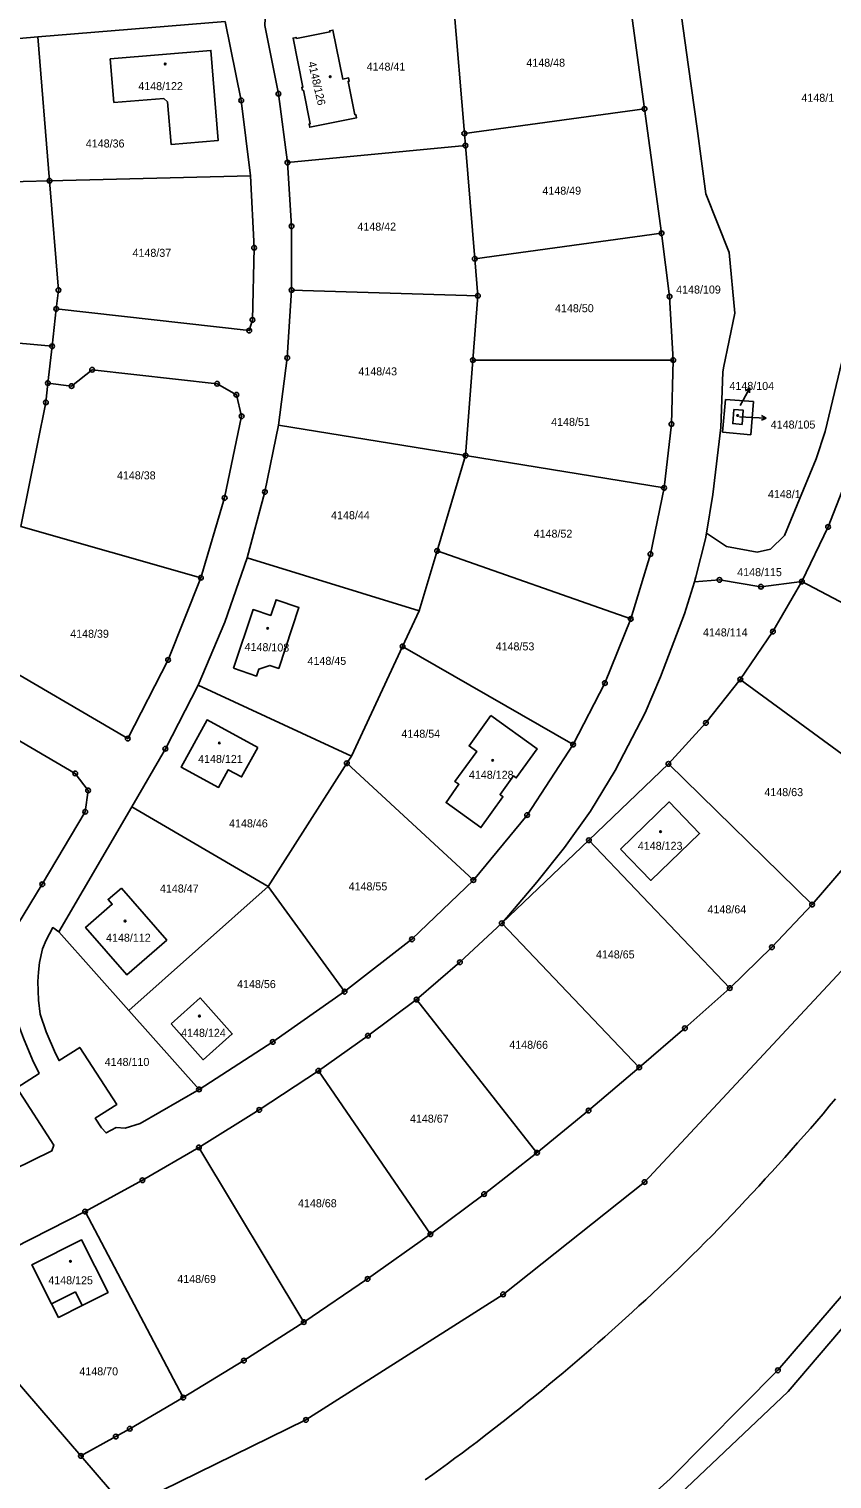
# Model space of a CAD drawing. Extents: x -733394 to -722299, y -1082822 to -1075049.
# Drawn here: x -728749.3 to -728578.8, y -1081434.3 to -1081126.2 of the extents above; entities that cross this region are included whole.
import ezdxf

# ---------------------------------------------------------------- set-up
doc = ezdxf.new("R2010")
doc.units = 0
for name, color, linetype in [('Hranice parcel', 7, 'Continuous'), ('Parcelní čísla', 7, 'Continuous'), ('Pop  PČ popisy', 7, 'Continuous'), ('Poz předměty', 7, 'Continuous'), ('Vnitřní kresba', 7, 'Continuous'), ('Značky bodu BP', 7, 'Continuous'), ('Značky budov', 7, 'Continuous')]:
    doc.layers.add(name, color=color, linetype=linetype)

msp = doc.modelspace()

# ---------------------------------------------------------------- linework, layer by layer
at = {"layer": 'Hranice parcel'}
for p, q in [((-728656.88, -1081148.41), (-728659.18, -1081120.67)), ((-728747.47, -1081127.91), (-728707.65, -1081124.65)), ((-728618.61, -1081143.18), (-728621.44, -1081122.45)), ((-728791.29, -1081131.5), (-728747.47, -1081127.91)), ((-728744.99, -1081158.46), (-728747.47, -1081127.91)), ((-728618.61, -1081143.18), (-728656.88, -1081148.41)), ((-728615, -1081169.61), (-728618.61, -1081143.18)), ((-728656.88, -1081148.41), (-728656.66, -1081150.97)), ((-728694.45, -1081154.6), (-728656.66, -1081150.97)), ((-728656.66, -1081150.97), (-728654.66, -1081175.03)), ((-728789.01, -1081159.56), (-728744.99, -1081158.46)), ((-728744.99, -1081158.46), (-728702.28, -1081157.4)), ((-728654.66, -1081175.03), (-728615, -1081169.61)), ((-728654.66, -1081175.03), (-728654.01, -1081182.89)), ((-728693.56, -1081181.69), (-728654.01, -1081182.89)), ((-728654.01, -1081182.89), (-728655.06, -1081196.55)), ((-728744.44, -1081193.63), (-728743.55, -1081185.68)), ((-728786.55, -1081189.82), (-728744.44, -1081193.63)), ((-728745.32, -1081201.46), (-728744.44, -1081193.63)), ((-728655.06, -1081196.55), (-728656.63, -1081216.84)), ((-728655.06, -1081196.55), (-728612.5, -1081196.55)), ((-728696.37, -1081210.37), (-728656.63, -1081216.84)), ((-728656.63, -1081216.84), (-728662.66, -1081237.09)), ((-728656.63, -1081216.84), (-728614.47, -1081223.7)), ((-728751.07, -1081231.9), (-728712.84, -1081242.8)), ((-728703.04, -1081238.54), (-728666.46, -1081249.83)), ((-728662.66, -1081237.09), (-728666.46, -1081249.83)), ((-728662.66, -1081237.09), (-728621.53, -1081251.55)), ((-728585.19, -1081243.6), (-728547.51, -1081263.58)), ((-728666.46, -1081249.83), (-728669.99, -1081257.39)), ((-728669.99, -1081257.39), (-728680.88, -1081280.71)), ((-728669.99, -1081257.39), (-728633.77, -1081278.23)), ((-728713.44, -1081265.59), (-728680.88, -1081280.71)), ((-728598.26, -1081264.4), (-728564.33, -1081289.3)), ((-728681.84, -1081282.2), (-728698.55, -1081308.42)), ((-728680.88, -1081280.71), (-728681.84, -1081282.2)), ((-728681.84, -1081282.2), (-728654.97, -1081307.04)), ((-728613.52, -1081282.34), (-728630.43, -1081298.57)), ((-728613.52, -1081282.34), (-728583.01, -1081312.24)), ((-728727.48, -1081291.48), (-728743.03, -1081318.03)), ((-728727.48, -1081291.48), (-728698.55, -1081308.42)), ((-728630.43, -1081298.57), (-728648.93, -1081316.2)), ((-728630.43, -1081298.57), (-728600.49, -1081329.99)), ((-728728.15, -1081334.76), (-728698.55, -1081308.42)), ((-728698.55, -1081308.42), (-728682.31, -1081330.74)), ((-728743.03, -1081318.03), (-728728.15, -1081334.76)), ((-728648.93, -1081316.2), (-728619.73, -1081346.84)), ((-728667.03, -1081332.41), (-728641.45, -1081364.96)), ((-728728.15, -1081334.76), (-728713.24, -1081351.51)), ((-728687.89, -1081347.54), (-728664.09, -1081382.28)), ((-728713.27, -1081363.83), (-728690.98, -1081400.95)), ((-728716.58, -1081416.99), (-728737.45, -1081377.46)), ((-728769.61, -1081393.06), (-728738.31, -1081429.37)), ((-728728.76, -1081440.45), (-728738.31, -1081429.37))]:
    msp.add_line(p, q, dxfattribs=at)
for points in [[(-728502.16, -1081044.8), (-728503.84, -1081129.16), (-728485.34, -1081131.45), (-728492.55, -1081170.1), (-728507.87, -1081209.04), (-728537.64, -1081268.56), (-728571.9, -1081321.09), (-728618.59, -1081371.19), (-728648.65, -1081395.05), (-728690.53, -1081421.73), (-728728.76, -1081440.45)], [(-728605.45, -1081233.33), (-728601.23, -1081236.18), (-728594.69, -1081237.34), (-728591.86, -1081236.75), (-728588.88, -1081233.8), (-728582.18, -1081217.56), (-728580.23, -1081211.76), (-728570.84, -1081172.34), (-728568.71, -1081162.14), (-728565.28, -1081140.35), (-728561.05, -1081095.68)], [(-728611.11, -1081121.03), (-728609.28, -1081134.26), (-728607.46, -1081147.33), (-728605.56, -1081161.23), (-728600.6, -1081173.67), (-728599.44, -1081186.58), (-728601.86, -1081198.18), (-728602.01, -1081199.15), (-728602.38, -1081210.88), (-728604.07, -1081225.15), (-728605.45, -1081233.33)], [(-728702.28, -1081157.4), (-728704.26, -1081141.39), (-728707.65, -1081124.65)], [(-728699.21, -1081123.95), (-728699.29, -1081125.48), (-728696.37, -1081139.96), (-728694.45, -1081154.6)], [(-728691.29, -1081139.28), (-728691.42, -1081138.62), (-728691.18, -1081138.56), (-728693.27, -1081128.14), (-728692.61, -1081128), (-728692.52, -1081128.23), (-728685.43, -1081126.82), (-728685.47, -1081126.57), (-728684.8, -1081126.45), (-728682.7, -1081136.86), (-728681.46, -1081136.62), (-728681.33, -1081137.29), (-728681.58, -1081137.35), (-728680.15, -1081144.45), (-728679.91, -1081144.4), (-728679.78, -1081145.08), (-728689.71, -1081147.09), (-728689.86, -1081146.42), (-728689.62, -1081146.36), (-728691.04, -1081139.24), (-728691.29, -1081139.28)], [(-728732.1, -1081132.54), (-728710.72, -1081130.77), (-728709.19, -1081149.91), (-728719.18, -1081150.74), (-728719.9, -1081141.7), (-728720.71, -1081140.99), (-728731.31, -1081141.82), (-728732.1, -1081132.54)], [(-728694.45, -1081154.6), (-728693.58, -1081168.13), (-728693.56, -1081181.69)], [(-728743.55, -1081185.68), (-728743.1, -1081181.7), (-728744.99, -1081158.46)], [(-728743.55, -1081185.68), (-728702.56, -1081190.29), (-728701.89, -1081188.02), (-728701.53, -1081172.7), (-728702.28, -1081157.4)], [(-728612.5, -1081196.55), (-728613.28, -1081183.05), (-728615, -1081169.61)], [(-728693.56, -1081181.69), (-728694.49, -1081196.08), (-728696.37, -1081210.37)], [(-728712.84, -1081242.8), (-728707.79, -1081225.83), (-728704.18, -1081208.49), (-728705.31, -1081203.92), (-728709.39, -1081201.58), (-728735.95, -1081198.62), (-728740.3, -1081202.07), (-728745.32, -1081201.46)], [(-728614.47, -1081223.7), (-728612.91, -1081210.17), (-728612.5, -1081196.55)], [(-728751.07, -1081231.9), (-728745.77, -1081205.55), (-728745.32, -1081201.46)], [(-728601.44, -1081204.92), (-728595.47, -1081205.37), (-728596.05, -1081212.42), (-728602.02, -1081211.85), (-728601.44, -1081204.92)], [(-728599.61, -1081207.06), (-728597.63, -1081207.21), (-728597.88, -1081210.24), (-728599.86, -1081210.05), (-728599.61, -1081207.06)], [(-728696.37, -1081210.37), (-728699.23, -1081224.57), (-728703.04, -1081238.54)], [(-728574.93, -1081220.03), (-728579.61, -1081232.01), (-728585.19, -1081243.6)], [(-728621.53, -1081251.55), (-728617.37, -1081237.79), (-728614.47, -1081223.7)], [(-728608.02, -1081243.64), (-728607.7, -1081242.6), (-728605.65, -1081234.5), (-728605.45, -1081233.33)], [(-728703.04, -1081238.54), (-728707.78, -1081252.24), (-728713.44, -1081265.59)], [(-728757.97, -1081259.66), (-728728.38, -1081276.98), (-728719.8, -1081260.26), (-728712.84, -1081242.8)], [(-728648.93, -1081316.2), (-728647.46, -1081314.48), (-728641.5, -1081307.46), (-728635.62, -1081300.08), (-728630.07, -1081292.37), (-728624.81, -1081283.74), (-728618.46, -1081271.53), (-728615.22, -1081263.88), (-728610.09, -1081250.49), (-728608.02, -1081243.64)], [(-728585.19, -1081243.6), (-728593.87, -1081244.71), (-728602.69, -1081243.25), (-728608.02, -1081243.64)], [(-728585.19, -1081243.6), (-728591.34, -1081254.24), (-728598.26, -1081264.4)], [(-728705.91, -1081262.03), (-728701.77, -1081249.56), (-728698, -1081250.82), (-728696.87, -1081247.49), (-728692.01, -1081249.13), (-728696.31, -1081262.07), (-728698.2, -1081261.44), (-728700.56, -1081262.24), (-728701.06, -1081263.68), (-728705.91, -1081262.03)], [(-728633.77, -1081278.23), (-728627.03, -1081265.17), (-728621.53, -1081251.55)], [(-728713.44, -1081265.59), (-728720.39, -1081279.12), (-728727.48, -1081291.48)], [(-728598.26, -1081264.4), (-728605.57, -1081273.64), (-728613.52, -1081282.34)], [(-728700.77, -1081278.86), (-728704.18, -1081285.11), (-728707.02, -1081283.59), (-728709.08, -1081287.36), (-728717, -1081283.06), (-728711.52, -1081273.01), (-728700.77, -1081278.86)], [(-728651.28, -1081272.08), (-728641.42, -1081279.14), (-728645.84, -1081285.33), (-728646.45, -1081284.9), (-728649.29, -1081288.88), (-728648.68, -1081289.32), (-728653.35, -1081295.87), (-728660.76, -1081290.57), (-728658.04, -1081286.69), (-728658.88, -1081286.1), (-728654.26, -1081279.69), (-728655.87, -1081278.52), (-728651.28, -1081272.08)], [(-728755.89, -1081323.18), (-728746.52, -1081307.93), (-728737.41, -1081292.52), (-728736.8, -1081288), (-728739.54, -1081284.36), (-728755.11, -1081275.24), (-728759.47, -1081277.36), (-728766.06, -1081273.47)], [(-728654.97, -1081307.04), (-728643.56, -1081293.23), (-728633.77, -1081278.23)], [(-728623.74, -1081300.44), (-728613.38, -1081290.42), (-728606.91, -1081297.13), (-728617.28, -1081307.12), (-728623.74, -1081300.44)], [(-728583.01, -1081312.24), (-728573.39, -1081301.02), (-728564.33, -1081289.3)], [(-728729.71, -1081308.72), (-728720.09, -1081319.8), (-728728.56, -1081327.17), (-728737.33, -1081317.09), (-728731.67, -1081312.16), (-728732.54, -1081311.16), (-728729.71, -1081308.72)], [(-728682.31, -1081330.74), (-728668, -1081319.62), (-728654.97, -1081307.04)], [(-728600.49, -1081329.99), (-728591.56, -1081321.3), (-728583.01, -1081312.24)], [(-728713.24, -1081351.51), (-728725.77, -1081358.75), (-728728.9, -1081359.71), (-728730.87, -1081359.61), (-728732.96, -1081360.74), (-728733.93, -1081359.7), (-728735.27, -1081357.62), (-728730.72, -1081354.71), (-728738.56, -1081342.58), (-728742.95, -1081345.39), (-728743.7, -1081343.9), (-728745.67, -1081339.31), (-728746.97, -1081335.52), (-728747.3, -1081332.55), (-728747.44, -1081328.57), (-728747.36, -1081326.58), (-728747.11, -1081324.58), (-728746.46, -1081321.65), (-728745.69, -1081319.77), (-728744.32, -1081317.14), (-728743.03, -1081318.03)], [(-728648.93, -1081316.2), (-728657.82, -1081324.48), (-728667.03, -1081332.41)], [(-728755.89, -1081323.18), (-728752.36, -1081325.85), (-728752.47, -1081327.85), (-728752.41, -1081331.88), (-728752.05, -1081335.84), (-728751.57, -1081337.8), (-728750.55, -1081340.65), (-728748.61, -1081345.25), (-728747.21, -1081348.11), (-728751.94, -1081351.15), (-728744.04, -1081363.34), (-728744.5, -1081364.57), (-728752.7, -1081368.57), (-728756.29, -1081370.94), (-728763.02, -1081377.06), (-728765.89, -1081379.72), (-728774.87, -1081383.98), (-728776.51, -1081385.05)], [(-728713.24, -1081351.51), (-728697.58, -1081341.42), (-728682.31, -1081330.74)], [(-728619.73, -1081346.84), (-728610.04, -1081338.5), (-728600.49, -1081329.99)], [(-728719.16, -1081337.55), (-728713, -1081332.06), (-728706.19, -1081339.73), (-728712.35, -1081345.21), (-728719.16, -1081337.55)], [(-728667.03, -1081332.41), (-728677.36, -1081340.1), (-728687.89, -1081347.54)], [(-728641.45, -1081364.96), (-728630.5, -1081356.01), (-728619.73, -1081346.84)], [(-728687.89, -1081347.54), (-728700.46, -1081355.87), (-728713.27, -1081363.83)], [(-728713.27, -1081363.83), (-728725.27, -1081370.81), (-728737.45, -1081377.46)], [(-728664.09, -1081382.28), (-728652.68, -1081373.74), (-728641.45, -1081364.96)], [(-728737.45, -1081377.46), (-728752.6, -1081385.14), (-728762.68, -1081389.83), (-728769.61, -1081393.06)], [(-728684.17, -1081496.93), (-728675.68, -1081490.38), (-728613.13, -1081434.22), (-728590.29, -1081411.19), (-728561.99, -1081378.22)], [(-728738.04, -1081397.4), (-728743.08, -1081399.95), (-728744.55, -1081397.07), (-728748.75, -1081388.81), (-728738.19, -1081383.48), (-728732.54, -1081394.63), (-728738.04, -1081397.4)], [(-728690.98, -1081400.95), (-728677.42, -1081391.78), (-728664.09, -1081382.28)], [(-728563.78, -1081387.23), (-728588.13, -1081415.66), (-728615.12, -1081441.36), (-728678.05, -1081496.71)], [(-728716.58, -1081416.99), (-728703.69, -1081409.11), (-728690.98, -1081400.95)], [(-728738.31, -1081429.37), (-728730.92, -1081425.26), (-728727.95, -1081423.61), (-728716.58, -1081416.99)]]:
    msp.add_lwpolyline(points, dxfattribs=at)
at = {"layer": 'Pop  PČ popisy'}
for p, q in [((-728598.26, -1081206.19), (-728597.68, -1081205.07)), ((-728597.68, -1081205.07), (-728596.27, -1081202.42)), ((-728596.27, -1081202.42), (-728597.18, -1081203.07)), ((-728596.27, -1081202.42), (-728596.3, -1081203.54)), ((-728592.76, -1081208.91), (-728593.74, -1081208.35)), ((-728598.46, -1081208.59), (-728595.76, -1081208.75)), ((-728595.76, -1081208.75), (-728592.76, -1081208.91)), ((-728592.76, -1081208.91), (-728593.79, -1081209.35))]:
    msp.add_line(p, q, dxfattribs=at)
at = {"layer": 'Poz předměty'}
for points in [[(-728605.7, -1081383.99), (-728604.26, -1081382.52), (-728602.83, -1081381.04), (-728601.41, -1081379.56), (-728599.98, -1081378.07), (-728598.57, -1081376.57), (-728597.16, -1081375.07), (-728595.76, -1081373.57), (-728594.36, -1081372.06), (-728592.97, -1081370.54), (-728591.58, -1081369.02), (-728590.2, -1081367.5), (-728588.83, -1081365.97), (-728587.46, -1081364.43), (-728586.1, -1081362.89), (-728584.74, -1081361.34), (-728583.39, -1081359.79), (-728582.04, -1081358.23), (-728580.7, -1081356.67), (-728579.37, -1081355.1), (-728578.04, -1081353.53)], [(-728665.17, -1081434.48), (-728663.59, -1081433.34), (-728662.01, -1081432.19), (-728660.44, -1081431.04), (-728658.87, -1081429.88), (-728657.3, -1081428.71), (-728655.74, -1081427.53), (-728654.19, -1081426.35), (-728652.64, -1081425.17), (-728651.09, -1081423.97), (-728649.55, -1081422.77), (-728648.01, -1081421.57), (-728646.48, -1081420.36), (-728644.96, -1081419.14), (-728643.44, -1081417.91), (-728641.92, -1081416.68), (-728640.41, -1081415.45), (-728638.9, -1081414.21), (-728637.4, -1081412.96), (-728635.91, -1081411.7), (-728634.41, -1081410.44), (-728632.93, -1081409.17), (-728631.45, -1081407.9), (-728629.97, -1081406.62), (-728628.5, -1081405.34), (-728627.04, -1081404.05), (-728625.58, -1081402.75), (-728624.12, -1081401.45), (-728622.67, -1081400.14), (-728621.23, -1081398.83), (-728619.79, -1081397.51), (-728618.36, -1081396.18), (-728616.93, -1081394.85), (-728615.51, -1081393.51), (-728614.09, -1081392.17), (-728612.68, -1081390.82), (-728611.27, -1081389.47), (-728609.87, -1081388.1), (-728608.47, -1081386.74), (-728607.08, -1081385.37), (-728605.7, -1081383.99)]]:
    msp.add_lwpolyline(points, dxfattribs=at)
at = {"layer": 'Vnitřní kresba'}
for p, q in [((-728744.55, -1081397.07), (-728739.49, -1081394.52)), ((-728739.49, -1081394.52), (-728738.04, -1081397.4))]:
    msp.add_line(p, q, dxfattribs=at)
at = {"layer": 'Značky bodu BP'}
for centre, radius in [((-728696.37, -1081139.96), 0.5), ((-728696.37, -1081139.96), 0.0303), ((-728704.26, -1081141.39), 0.5), ((-728704.26, -1081141.39), 0.0303), ((-728618.61, -1081143.18), 0.5), ((-728618.61, -1081143.18), 0.0303), ((-728656.88, -1081148.41), 0.5), ((-728656.88, -1081148.41), 0.0303), ((-728656.66, -1081150.97), 0.5), ((-728656.66, -1081150.97), 0.0303), ((-728694.45, -1081154.6), 0.5), ((-728694.45, -1081154.6), 0.0303), ((-728744.99, -1081158.46), 0.5), ((-728744.99, -1081158.46), 0.0303), ((-728693.58, -1081168.13), 0.5), ((-728693.58, -1081168.13), 0.0303), ((-728615, -1081169.61), 0.5), ((-728615, -1081169.61), 0.0303), ((-728701.53, -1081172.7), 0.5), ((-728701.53, -1081172.7), 0.0303), ((-728654.66, -1081175.03), 0.5), ((-728654.66, -1081175.03), 0.0303), ((-728743.1, -1081181.7), 0.5), ((-728743.1, -1081181.7), 0.0303), ((-728693.56, -1081181.69), 0.5), ((-728693.56, -1081181.69), 0.0303), ((-728654.01, -1081182.89), 0.5), ((-728654.01, -1081182.89), 0.0303), ((-728613.28, -1081183.05), 0.5), ((-728613.28, -1081183.05), 0.0303), ((-728743.55, -1081185.68), 0.5), ((-728743.55, -1081185.68), 0.0303), ((-728702.56, -1081190.29), 0.5), ((-728701.89, -1081188.02), 0.5), ((-728701.89, -1081188.02), 0.0303), ((-728702.56, -1081190.29), 0.0303), ((-728744.44, -1081193.63), 0.5), ((-728744.44, -1081193.63), 0.0303), ((-728694.49, -1081196.08), 0.5), ((-728694.49, -1081196.08), 0.0303), ((-728655.06, -1081196.55), 0.5), ((-728612.5, -1081196.55), 0.5), ((-728735.95, -1081198.62), 0.5), ((-728735.95, -1081198.62), 0.0303), ((-728655.06, -1081196.55), 0.0303), ((-728612.5, -1081196.55), 0.0303), ((-728745.32, -1081201.46), 0.5), ((-728745.32, -1081201.46), 0.0303), ((-728740.3, -1081202.07), 0.5), ((-728740.3, -1081202.07), 0.0303), ((-728709.39, -1081201.58), 0.5), ((-728709.39, -1081201.58), 0.0303), ((-728745.77, -1081205.55), 0.5), ((-728705.31, -1081203.92), 0.5), ((-728705.31, -1081203.92), 0.0303), ((-728745.77, -1081205.55), 0.0303), ((-728704.18, -1081208.49), 0.5), ((-728704.18, -1081208.49), 0.0303), ((-728612.91, -1081210.17), 0.5), ((-728612.91, -1081210.17), 0.0303), ((-728656.63, -1081216.84), 0.5), ((-728656.63, -1081216.84), 0.0303), ((-728614.47, -1081223.7), 0.5), ((-728614.47, -1081223.7), 0.0303), ((-728707.79, -1081225.83), 0.5), ((-728707.79, -1081225.83), 0.0303), ((-728699.23, -1081224.57), 0.5), ((-728699.23, -1081224.57), 0.0303), ((-728579.61, -1081232.01), 0.5), ((-728579.61, -1081232.01), 0.0303), ((-728662.66, -1081237.09), 0.5), ((-728662.66, -1081237.09), 0.0303), ((-728617.37, -1081237.79), 0.5), ((-728617.37, -1081237.79), 0.0303), ((-728712.84, -1081242.8), 0.5), ((-728712.84, -1081242.8), 0.0303), ((-728602.69, -1081243.25), 0.5), ((-728602.69, -1081243.25), 0.0303), ((-728593.87, -1081244.71), 0.5), ((-728593.87, -1081244.71), 0.0303), ((-728585.19, -1081243.6), 0.5), ((-728585.19, -1081243.6), 0.0303), ((-728621.53, -1081251.55), 0.5), ((-728621.53, -1081251.55), 0.0303), ((-728591.34, -1081254.24), 0.5), ((-728591.34, -1081254.24), 0.0303), ((-728669.99, -1081257.39), 0.5), ((-728669.99, -1081257.39), 0.0303), ((-728719.8, -1081260.26), 0.5), ((-728719.8, -1081260.26), 0.0303), ((-728627.03, -1081265.17), 0.5), ((-728627.03, -1081265.17), 0.0303), ((-728598.26, -1081264.4), 0.5), ((-728598.26, -1081264.4), 0.0303), ((-728605.57, -1081273.64), 0.5), ((-728605.57, -1081273.64), 0.0303), ((-728728.38, -1081276.98), 0.5), ((-728728.38, -1081276.98), 0.0303), ((-728720.39, -1081279.12), 0.5), ((-728720.39, -1081279.12), 0.0303), ((-728633.77, -1081278.23), 0.5), ((-728633.77, -1081278.23), 0.0303), ((-728681.84, -1081282.2), 0.5), ((-728681.84, -1081282.2), 0.0303), ((-728613.52, -1081282.34), 0.5), ((-728613.52, -1081282.34), 0.0303), ((-728739.54, -1081284.36), 0.5), ((-728739.54, -1081284.36), 0.0303), ((-728736.8, -1081288), 0.5), ((-728736.8, -1081288), 0.0303), ((-728737.41, -1081292.52), 0.5), ((-728737.41, -1081292.52), 0.0303), ((-728643.56, -1081293.23), 0.5), ((-728643.56, -1081293.23), 0.0303), ((-728630.43, -1081298.57), 0.5), ((-728630.43, -1081298.57), 0.0303), ((-728654.97, -1081307.04), 0.5), ((-728746.52, -1081307.93), 0.5), ((-728746.52, -1081307.93), 0.0303), ((-728654.97, -1081307.04), 0.0303), ((-728583.01, -1081312.24), 0.5), ((-728583.01, -1081312.24), 0.0303), ((-728648.93, -1081316.2), 0.5), ((-728648.93, -1081316.2), 0.0303), ((-728668, -1081319.62), 0.5), ((-728668, -1081319.62), 0.0303), ((-728591.56, -1081321.3), 0.5), ((-728591.56, -1081321.3), 0.0303), ((-728657.82, -1081324.48), 0.5), ((-728657.82, -1081324.48), 0.0303), ((-728682.31, -1081330.74), 0.5), ((-728682.31, -1081330.74), 0.0303), ((-728600.49, -1081329.99), 0.5), ((-728600.49, -1081329.99), 0.0303), ((-728667.03, -1081332.41), 0.5), ((-728667.03, -1081332.41), 0.0303), ((-728677.36, -1081340.1), 0.5), ((-728677.36, -1081340.1), 0.0303), ((-728610.04, -1081338.5), 0.5), ((-728610.04, -1081338.5), 0.0303), ((-728697.58, -1081341.42), 0.5), ((-728697.58, -1081341.42), 0.0303), ((-728619.73, -1081346.84), 0.5), ((-728619.73, -1081346.84), 0.0303), ((-728687.89, -1081347.54), 0.5), ((-728687.89, -1081347.54), 0.0303), ((-728713.24, -1081351.51), 0.5), ((-728713.24, -1081351.51), 0.0303), ((-728700.46, -1081355.87), 0.5), ((-728700.46, -1081355.87), 0.0303), ((-728630.5, -1081356.01), 0.5), ((-728630.5, -1081356.01), 0.0303), ((-728713.27, -1081363.83), 0.5), ((-728713.27, -1081363.83), 0.0303), ((-728641.45, -1081364.96), 0.5), ((-728641.45, -1081364.96), 0.0303), ((-728725.27, -1081370.81), 0.5), ((-728725.27, -1081370.81), 0.0303), ((-728618.59, -1081371.19), 0.5), ((-728618.59, -1081371.19), 0.0303), ((-728652.68, -1081373.74), 0.5), ((-728652.68, -1081373.74), 0.0303), ((-728737.45, -1081377.46), 0.5), ((-728737.45, -1081377.46), 0.0303), ((-728664.09, -1081382.28), 0.5), ((-728664.09, -1081382.28), 0.0303), ((-728677.42, -1081391.78), 0.5), ((-728677.42, -1081391.78), 0.0303), ((-728648.65, -1081395.05), 0.5), ((-728648.65, -1081395.05), 0.0303), ((-728690.98, -1081400.95), 0.5), ((-728690.98, -1081400.95), 0.0303), ((-728703.69, -1081409.11), 0.5), ((-728703.69, -1081409.11), 0.0303), ((-728590.29, -1081411.19), 0.5), ((-728590.29, -1081411.19), 0.0303), ((-728716.58, -1081416.99), 0.5), ((-728716.58, -1081416.99), 0.0303), ((-728727.95, -1081423.61), 0.5), ((-728727.95, -1081423.61), 0.0303), ((-728690.53, -1081421.73), 0.5), ((-728690.53, -1081421.73), 0.0303), ((-728730.92, -1081425.26), 0.5), ((-728730.92, -1081425.26), 0.0303), ((-728738.31, -1081429.37), 0.5), ((-728738.31, -1081429.37), 0.0303)]:
    msp.add_circle(centre, radius, dxfattribs=at)
at = {"layer": 'Značky budov'}
for centre in [(-728720.42, -1081133.66), (-728685.37, -1081136.36), (-728598.81, -1081208.33), (-728698.66, -1081253.56), (-728708.92, -1081277.91), (-728650.87, -1081281.6), (-728615.2, -1081296.74), (-728728.94, -1081315.75), (-728713.15, -1081335.93), (-728740.54, -1081388.05)]:
    msp.add_circle(centre, 0.175, dxfattribs=at)

# ---------------------------------------------------------------- texts
at = {"layer": 'Parcelní čísla'}
for s, rotation, p in [('4148/126', 283, (-728690.1, -1081133.33)), ('4148/108', 359, (-728703.57, -1081258.33))]:
    msp.add_text(s, height=1.7, rotation=rotation, dxfattribs=at).set_placement(p)
for s, p in [('4148/41', (-728677.63, -1081135.06)), ('4148/48', (-728643.71, -1081134.23)), ('4148/122', (-728726.14, -1081139.2)), ('4148/1', (-728585.28, -1081141.68)), ('4148/36', (-728737.28, -1081151.39)), ('4148/49', (-728640.3, -1081161.41)), ('4148/42', (-728679.59, -1081169.05)), ('4148/37', (-728727.36, -1081174.62)), ('4148/109', (-728611.89, -1081182.42)), ('4148/50', (-728637.62, -1081186.39)), ('4148/43', (-728679.39, -1081199.81)), ('4148/104', (-728600.57, -1081202.89)), ('4148/51', (-728638.44, -1081210.54)), ('4148/105', (-728591.8, -1081211.1)), ('4148/38', (-728730.67, -1081221.9)), ('4148/1', (-728592.4, -1081225.88)), ('4148/44', (-728685.18, -1081230.36)), ('4148/52', (-728642.16, -1081234.29)), ('4148/115', (-728598.92, -1081242.46)), ('4148/39', (-728740.6, -1081255.55)), ('4148/114', (-728606.2, -1081255.27)), ('4148/53', (-728650.23, -1081258.24)), ('4148/45', (-728690.19, -1081261.31)), ('4148/54', (-728670.24, -1081276.79)), ('4148/121', (-728713.43, -1081282.15)), ('4148/128', (-728655.91, -1081285.51)), ('4148/63', (-728593.15, -1081289.2)), ('4148/46', (-728706.85, -1081295.84)), ('4148/123', (-728620.03, -1081300.6)), ('4148/47', (-728721.54, -1081309.68)), ('4148/55', (-728681.46, -1081309.23)), ('4148/64', (-728605.23, -1081314.1)), ('4148/112', (-728732.98, -1081320.13)), ('4148/65', (-728628.93, -1081323.68)), ('4148/56', (-728705.15, -1081329.98)), ('4148/124', (-728717.03, -1081340.33)), ('4148/66', (-728647.33, -1081342.88)), ('4148/110', (-728733.27, -1081346.52)), ('4148/67', (-728668.43, -1081358.57)), ('4148/68', (-728692.21, -1081376.54)), ('4148/125', (-728745.25, -1081392.91)), ('4148/69', (-728717.85, -1081392.64)), ('4148/70', (-728738.65, -1081412.26))]:
    msp.add_text(s, height=1.7, dxfattribs=at).set_placement(p)

doc.saveas('drawing.dxf')
